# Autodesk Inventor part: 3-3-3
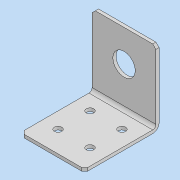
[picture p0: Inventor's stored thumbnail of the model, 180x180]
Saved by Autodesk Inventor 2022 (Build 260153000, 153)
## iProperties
Created: 2021-07
Part Number: 3-3-3
Material: 一般
Document SubType Name: Modeling
Designer: DesignLab
Density: 1 g/cm^3
Appearance: 既定
Author: DesignLab
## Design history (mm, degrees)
sketch "スケッチ1"
  geometry: L1 (0, 0)-(70, 0); L2 (70, 0)-(70, 70); L3 (70, 70)-(0, 70); L4 (0, 70)-(0, 0)
  constraints: 8 end point, 2 parallel, 1 horizontal, 1 perpendicular
  dimensions: "d0" = 70 distance of L3.end L2.end; "d1" = 70 distance of L2.end L1.end
extrude "押し出し1" new body sketch "スケッチ1" taper "d3" = 0 deg; stored distance "全幅" = 60
feature "シェル1" dims "d5" = 3
sketch "スケッチ2"
  geometry: L1 (0, -6)-(60, -6) reference; 3 further points
  constraints: 1 midpoint, 1 vertical alignment
  dimensions: "d6" = 40 distance from line of point (30, 34) L1
hole "穴1" sketch "スケッチ2" at (30, 34) diameter "d7" = 21; stored, may be unused: countersink angle "d11" = 90 deg, drill point angle "d13" = 118 deg; dims "d8" = 6, "d9" = 4, "d10" = 2, "d12" = 8
sketch "スケッチ3"
  geometry: L1 (15, -44)-(45, -44); L2 (45, -44)-(45, -14); L3 (45, -14)-(15, -14); L4 (15, -14)-(15, -44); L5 (15, -44)-(45, -14); L6 (45, -44)-(15, -14); L7 (60, 6)-(0, 6) reference; 4 further points
  constraints: 12 end point, 4 midpoint, 2 parallel, 1 horizontal, 1 perpendicular, 1 vertical alignment
  dimensions: "d14" = 30 distance of L3.end L2.end (= 0.5 x 全幅); "d15" = 30 distance of L2.end L1.end; "d16" = 20 distance between parallel lines of L3 L7
hole "穴2" sketch "スケッチ3" at (15, -44), (45, -44), (15, -14), (45, -14) diameter "d17" = 7; stored, may be unused: countersink angle "d21" = 90 deg, drill point angle "d23" = 118 deg; dims "d18" = 6, "d19" = 4, "d20" = 2, "d22" = 8
chamfer "面取り1" distance "d24" = 3; stored, may be unused: second distance "d25" = 2, angle "d26" = 45 deg
node "ソリッド1"
fillet "フィレット1" dims "d27" = 6
